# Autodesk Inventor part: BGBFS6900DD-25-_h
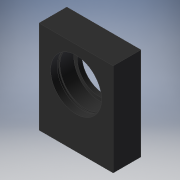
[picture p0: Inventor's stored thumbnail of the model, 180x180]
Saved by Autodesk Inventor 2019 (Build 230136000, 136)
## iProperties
Created: 2022-11
Part Number: BGBFS6900DD-25-_h
Material: Generic
Catalog Web Link: www.cadenas.de
Description: BGBFB, BGBF, BGBFA, BGBFSA, BGBFS_housing-Bearings with Housings - Bottom Mount - h Configurable
Vendor: MISUMI
Document SubType Name: Modeling
Designer: psAdmin
Manufacturer: MISUMI
Mass: 10.6692 g
Surface Area: 48.6357 cm^2
Volume: 10.6692 cm^3
Density: 1 g/cm^3
Appearance: PSOLRGB-175-175-175
Category: PARTsolutions
Company: MISUMI
Title: BGBFS6900DD-25-
Author: Cadenas PARTsolutions
Comments: Bearings with Housings - Bottom Mount - h Configurable
PSOL_IDENT_0: {$CADENAS_DATA/23d-libs/misumi/metric/12_bearing_holders/bgbfb/bgbfb_housing.prj},245 {VTYP=3D},{NB=
PSOL_IDENT_1: BGBFS6900DD-25-_h},{LINA=BGBFS6900DD-25-},{NN=BGBFB, BGBF, BGBFA, BGBFSA, BGBFS_housing},{DATE=18.09
PSOL_IDENT_2: .2019 08:57:38},{GEOMDATE=09.09.2019 09:39:18},{VERSION=},{LINEID=90},{WBVAR=MATB,MATH,STH,SEAL,HH,A
PSOL_IDENT_3: LT1,ALT2,ALT3},{WBNUMERIC=HH}  {NB=BGBFS6900DD-25-_h},{LINA=BGBFS6900DD-25-},{KT=DUMMY},{PN=BGBFS690
PSOL_IDENT_4: 0DD-25-},{TYPE=BGBFS},{MATB=SS},{MATBALG='S','Steel','SS','Stainless Steel'},{MATH=SUS304},{MATHALG='
PSOL_IDENT_5: 2017AA','2017 Aluminum Alloy','SUS304','304 Stainless Steel'},{STH=-},{STHALG='-','-'},{ARR=304 Stai
PSOL_IDENT_6: nless Steel},{ARR3D=-S},{BN=6900},{SEAL=DD},{SEALALG='ZZ','ZZ(Double Shielded)','VV','VV(Non-Contact
PSOL_IDENT_7: Sealed Rubber Seal)','DD','DD(Contact Sealed Rubber Seal)'},{HH=25},{HHALG=[25:50/1]},{DD=10},{D=22
PSOL_IDENT_8: },{DDHH=19},{B=6},{H=40},{H2=15},{L=32},{L1=20},{T=12},{M=M5},{M3D=5},{PITCH=0.8},{ALT1=},{KKC=0},{A
PSOL_IDENT_9: LT2=},{MM=1.15},{DD2=23},{ALT3=},{ALT1ALG= '', 'Bearings, Retaining Rings Assembled', '-NA'  , 'with
PSOL_IDENT_10: NA (Bearings, Retaining Rings Not Assembled)'},{ALT2ALG= '','w/o KCC (C2 Chamfer)','-KCC','with KCC
PSOL_IDENT_11: (C2 Chamfer)' },{ALT3ALG= '','w/o KKC (C Chamfer)','-KKC','with KKC (C Chamfer)' }
NB: BGBFS6900DD-25-_h
NN: BGBFB, BGBF, BGBFA, BGBFSA, BGBFS_housing
NT: Bearings with Housings - Bottom Mount - h Configurable
NBSYN: $PN._h
LINA: BGBFS6900DD-25-
CATALOG: Misumi
PN: BGBFS6900DD-25-
MATB: Stainless Steel
MATH: 304 Stainless Steel
STH: -
ARR: 304 Stainless Steel
BN: 6900
SEAL: DD(Contact Sealed Rubber Seal)
HH: 25
DD: 10
D: 22
DDHH: 19
B: 6
H: 40
L: 32
L1: 20
T: 12
M: M5
ALT1: Bearings, Retaining Rings Assembled
ALT2: w/o KCC (C2 Chamfer)
ALT3: w/o KKC (C Chamfer)
SUPPLIER: MISUMI
ARTICLENO: BGBFS6900DD-25-_h
BOMINFO: BGBFS6900DD-25-
CREATOR: CADENAS GmbH
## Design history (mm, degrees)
sketch "_____1"
  geometry: L1 (-16, 15)-(-16, -25); L2 (-16, -25)-(16, -25); L3 (16, -25)-(16, 15); L4 (16, 15)-(-16, 15)
  constraints: 8 end point
extrude "Extrusion1" join sketch "_____1" stored distance "d0" = 12; taper "d1" = 0 deg
sketch "Sketch_2"
  geometry: L1 (0, -6)-(0, 6); L2 (0, 6)-(11, 6); L3 (11, 6)-(11, 3.15); L4 (11, 3.15)-(11.5, 3.15); L5 (11.5, 3.15)-(11.5, 2); L6 (11.5, 2)-(11, 2); L7 (11, 2)-(11, -4); L8 (11, -4)-(9.5, -4); L9 (9.5, -4)-(9.5, -6); L10 (9.5, -6)-(0, -6); L11 (0, -6)-(0, 6)
  constraints: 22 end point
revolve "Revolution1" sketch "Sketch_2" stored, may be unused: angle "d2" = 360 deg
sketch "Sketch3"
  geometry: 1 further point
hole "Hole1" sketch "Sketch3" at (6, -6) diameter "d3" = 4.134; stored, may be unused: countersink angle "d7" = 90 deg, drill point angle "d9" = 120 deg; dims "d4" = 7.5, "d5" = 5, "d6" = 2, "d8" = 10
pattern_linear "Rectangular Pattern1" dims "d12" = 20, "d15" = 0
node "to_bearing_XY"
node "to_bearing_YZ"
node "to_bearing_ZX"
node "to_bearing_X"
node "to_bearing_Y"
node "to_bearing_Z"
node "to_bearing_Center"
node "to_ring_XY"
node "to_ring_YZ"
node "to_ring_ZX"
node "to_ring_X"
node "to_ring_Y"
node "to_ring_Z"
node "to_ring_Center"
body "Solid1"
other parameters: "d16" = 0, "d17" = 0
